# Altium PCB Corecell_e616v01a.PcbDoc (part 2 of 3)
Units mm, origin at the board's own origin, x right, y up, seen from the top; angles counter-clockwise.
Board outline 72.95 x 30.9 mm, 4 copper layers (Top Layer, MidLayer1 - GND, MidLayer2, Bottom Layer), stack 0.637 mm thick; 233 components, 174 nets, 666 pads, 1160 vias.
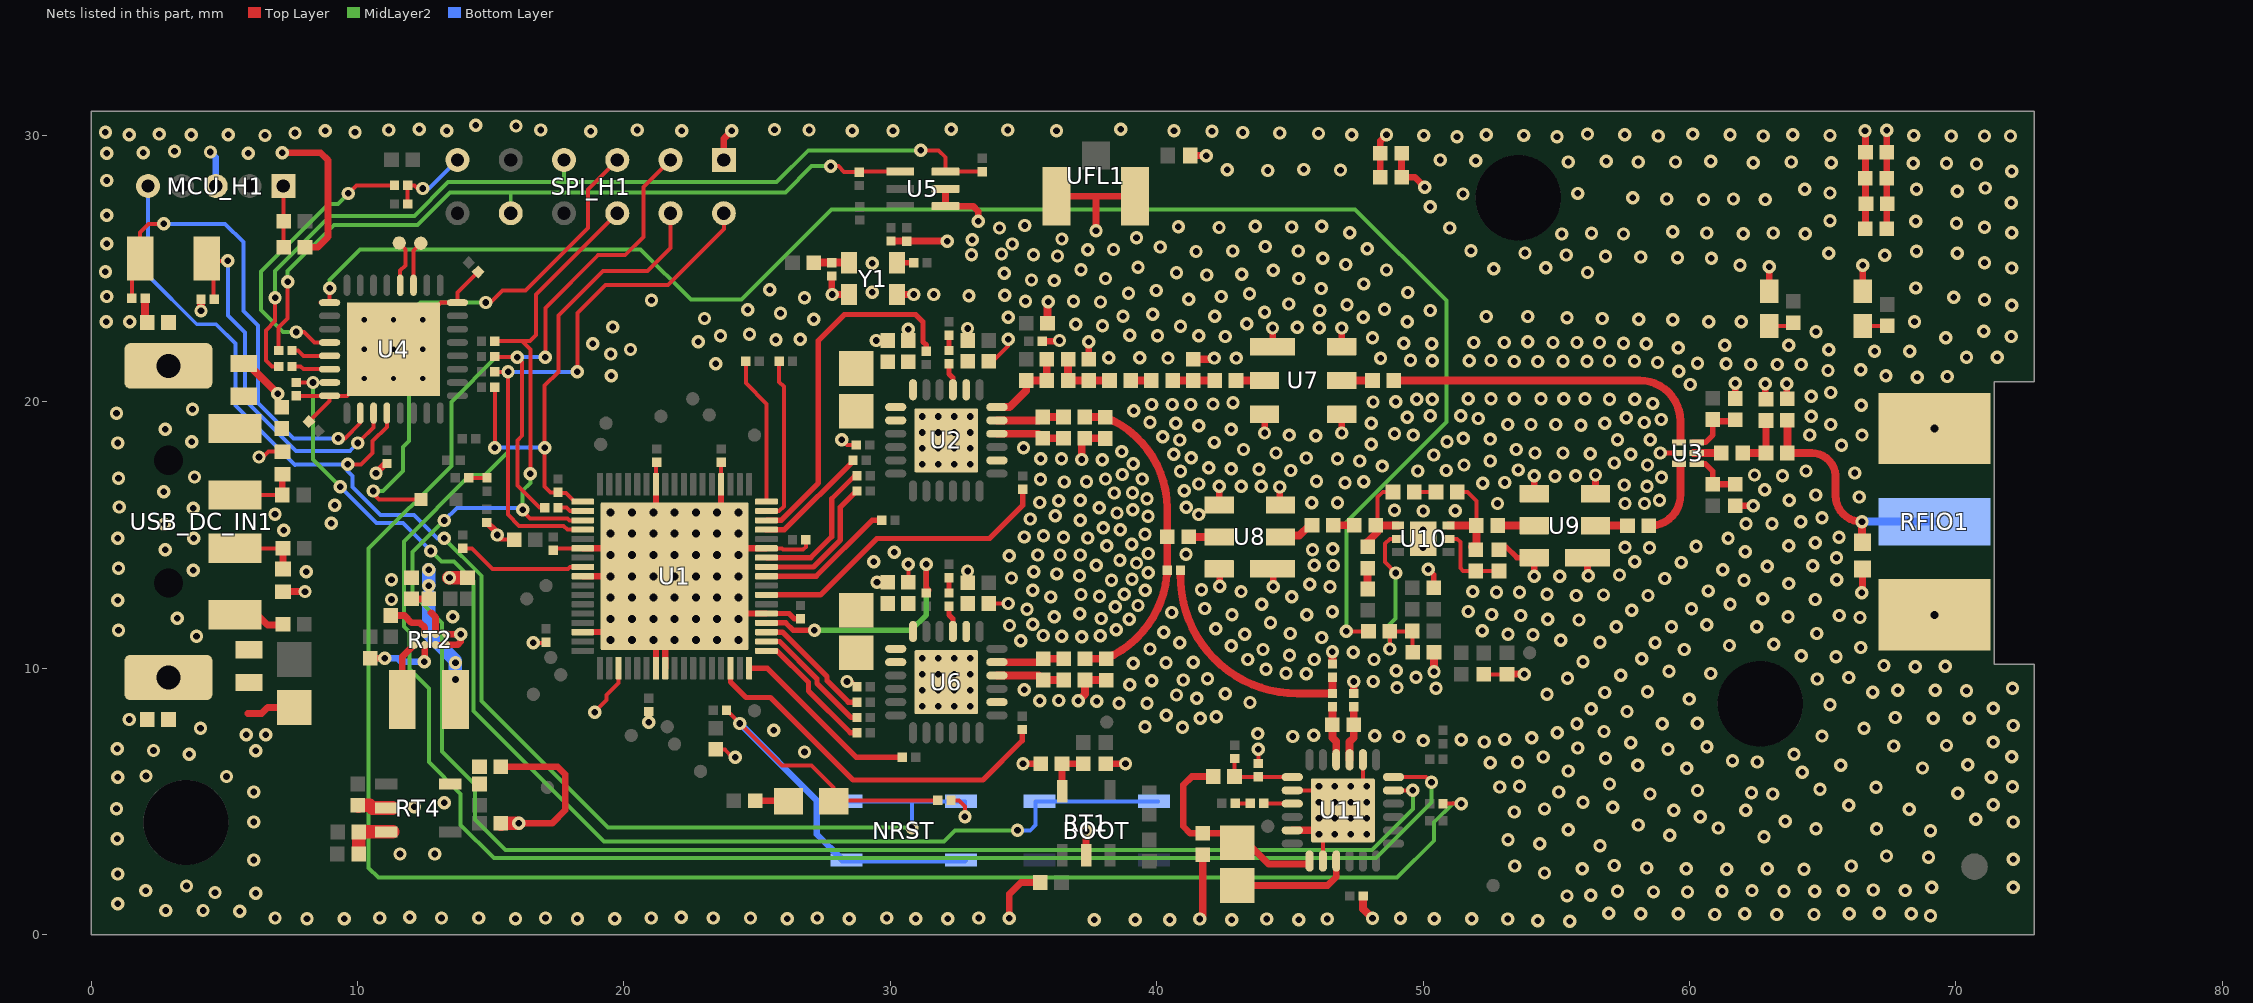
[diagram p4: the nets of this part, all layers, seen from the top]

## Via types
v1: diameter 0.5, hole 0.25, Top Layer to Bottom Layer, tented both sides, 1086 vias
v2: diameter 0.6, hole 0.3, Top Layer to Bottom Layer, tented top, 49 vias
v3: diameter 0.5, hole 0.25, Top Layer to Bottom Layer, 16 vias
v4: diameter 0.5, hole 0.2, Top Layer to Bottom Layer, 9 vias

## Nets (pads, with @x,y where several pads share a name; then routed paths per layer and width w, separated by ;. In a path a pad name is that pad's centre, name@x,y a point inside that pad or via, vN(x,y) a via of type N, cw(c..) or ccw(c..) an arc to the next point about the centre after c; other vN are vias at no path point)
GND: 433MHz.1 433MHz.2 490MHz.1 490MHz.2 920MHz.1 920MHz.2 C1.1 C2.1 C3.1 C4.1 C5.1 C6.1 C7.1 C8.1 C9.1 C10.1 C12.1 C13.1 C14.1 C15.2 C16.2 C17.1 C18.1 C21.1 C22.1 C23.1 C24.1 C29.1 C31.1 C33.2 C34.2 C35.1 C36.1 C37.1 C38.2 C39.2 C40.2 C41.1 C44.1 C45.1 C46.1 C47.1 C48.1 C49.2 C50.1 C51.2 C52.1 C53.1 C54.1 C55.1 C56.1 C58.2 C59.2 C60.2 C61.1 C67.1 C68.2 C69.1 C72.1 C73.1 C74.1 C75.1 D1.2 D2.2 D3.2 D4.2 D6.2 D11.2 FB6.1 FB7.2 FB15.1 LED_PWR.2 LED_RX.2 LED_TX.2 MCU_H1.3 NRST.2 Other.1 Other.2 R8.1 R30.1 R38.2 R59.2 RFIO1.2 RT1.2 RT2.B2 RT2.C1 RT2.D1 RT2.D2 RT4.2 SPI_H1.1 SX1302.1 SX1302.2 SX1303.1 SX1303.2 U1.6 U1.9 U1.15 U1.20 U1.24 U1.25 U1.39 U1.46 U1.55 U1.62 U1.69 U2.7 U2.20 U2.25 U3.2 U4.16 U4.32 U4.33 U5.4 U5.5 U6.7 U6.20 U6.25 U7.1 U7.3 U7.4 U7.6 U8.1 U8.3 U8.4 U8.6 U9.1 U9.3 U9.4 U9.6 U10.7 U11.2 U11.5 U11.8 U11.20 U11.25 UFL1.1 UFL1.2 Y1.1 Y1.2 | length 170
  Top Layer w0.15: v1(6.3,17.925) 6.45,17.925 6.65,18.125 D3.2@7.175,18.125 ; R30.1@7.7,20.225 U4.32@8.95,20.225 ; C12.1@8.173,19.252 8.95,20.029 U4.32@8.95,20.225 ; C16.2@11.25,11.975 C16.2@11.45,11.775 ; C54.1@14.527,24.873 13.75,24.096 U4.16@13.75,23.725 13.125,23.725 13,23.6 12.975,23.6 v4(12.45,23.075) v4(11.35,21.975) v4(10.25,20.875) 9.6,20.225 U4.32@8.95,20.225 ; v1@15.24,14.925 15.34,14.825 C4.1@15.875,14.825 ; v1(16.6,10.95) 17.05,10.95 C7.1@17.075,10.975 ; C5.1@17.35,14.425 17.425,14.5 U1.6@18.45,14.5 ; v1(18.9,8.35) 19.35,8.8 19.35,9 19.8,9.45 U1.20@19.8,10 ; U1.69@19.8,11.35 v2(20.3,11.85) v2(21.1,12.65) 21.2,12.75 21.55,13.1 v2(21.9,13.45) ; U1.69@20.85,14.5 v2(21.1,14.25) ; v1@20.925,7.925 v1(20.925,7.975) C8.1@20.925,8.375 ; U1.69@21.2,14.15 v2(21.9,13.45) ; U1.62@21.2,16.9 21.2,17.7 C1.1@21.225,17.725 ; U1.69@23.3,12.05 v2(22.7,12.65) v2(21.9,13.45) ; C10.1@23.45,6.95 23.784,6.95 24.079,6.655 v1(24.181,6.655) ; C2.1@23.625,17.8 23.65,17.775 C2.1@23.65,17.725 U1.55@23.65,16.9 ; U1.69@23.65,15.2 v2(23.5,15.05) 22.95,14.5 v2(22.7,14.25) v2(21.9,13.45) ; C9.1@23.925,8.35 C9.1@23.85,8.425 v1(24.35,7.925) 25.925,6.35 27.043,6.35 27.873,5.52 27.875,5.52 LED_PWR.2@27.875,5 27.912,5.037 R38.2@31.779,5.037 ; U1.46@25.35,14.5 25.925,14.5 25.975,14.45 26.725,14.45 26.825,14.55 C3.1@26.825,14.825 ; v1(28.175,18.575) 28.375,18.375 C37.1@28.725,18.375 ; C46.1@30.675,13.225 v1(30.675,13.9) ; C41.1@33.7,12.425 v1(34.425,12.425) ; C23.1@33.7,21.525 33.85,21.525 34.425,22.1 v1(34.425,22.35) ; v1@34.976,6.403 v1(34.982,6.409) ; C31.1@43.815,6.422 v1(43.815,6.95) ; U11.2@45.09,5.412 46.09,5.412 46.24,5.412 v3(46.69,4.962) U11.25@46.99,4.662 v3(47.29,4.962) 47.74,5.412 47.74,5.562 U11.20@47.74,6.562 ; U11.8@46.24,2.762 U11.25@46.24,3.762 ; v1(46.596,10.612) v1@46.609,10.625 ; C14.1@52.273,9.769 53.143,9.769 C61.1@53.15,9.777 ; v1@53.795,9.777 v1(53.797,9.775)
  Top Layer w0.152: v1(28.375,9.5) 28.55,9.5 C47.1@28.75,9.3 ; C36.1@30.675,22.3 v1(30.675,22.725)
  Top Layer w0.2: U1.39@25.35,12.05 26.2,12.05 26.4,11.85 C6.1@26.625,11.85 ; v1(50.19,13.716) 50.398,13.509 C68.2@50.398,13.015 ; C67.1@52.682,14.551 52.85,14.551 53.121,14.551 53.521,14.15 U9.6@54.175,14.15 ; v1(58.9,18.077) 59.61,18.077 59.758,18.077 U3.2@59.76,18.075
  Top Layer w0.203: RT2.C1@12.925,10.875 RT2.D1@13.325,10.875
  Top Layer w0.229: U1.15@18.45,11.35 19.5,11.35 U1.69@19.8,11.35 ; U1.9@18.45,13.45 v2(19.5,13.45) v2(20.3,13.45) v2(21.1,13.45) v2(21.9,13.45) ; U1.6@18.45,14.5 19.5,14.5 20.3,14.5 U1.69@20.85,14.5 ; U1.24@21.2,10 21.2,11.05 21.2,11.85 21.2,12.65 U1.69@21.2,12.75 ; U1.69@21.2,14.15 21.2,14.25 21.2,15.05 21.2,15.85 U1.62@21.2,16.9 ; U1.25@21.55,10 21.55,11.05 21.55,11.85 21.55,12.65 U1.69@21.55,13.1 ; U1.69@22.95,14.5 23.5,14.5 24.3,14.5 U1.46@25.35,14.5 ; U1.69@23.3,12.05 23.5,12.05 24.3,12.05 U1.39@25.35,12.05 ; U1.69@23.65,15.2 23.65,15.85 U1.55@23.65,16.9
  Top Layer w0.25: C48.1@27.8,24.725 27.8,24.05 v1(27.825,24.025) Y1.1@28.45,24.025 ; Y1.2@30.25,24.025 v1(30.875,24.025) ; C18.1@35.7,22.275 36.325,22.275 v1(36.35,22.3) ; C21.1@37.45,21.6 v1(37.45,22.25) ; U8.4@42.348,16.127 v1(42.348,16.827) ; v1(42.373,13.077) 42.373,13.727 U8.6@42.373,13.752 ; v1(44.05,18.83) U7.3@44.05,19.53 ; U7.1@44.35,22.07 v1(44.35,22.77) ; v1(44.373,13.052) 44.373,13.727 U8.1@44.373,13.752 ; U8.3@44.623,16.102 44.623,16.127 v1(44.623,16.802) ; v1(46.95,18.83) U7.4@46.95,19.53 ; U7.6@46.95,22.07 v1(46.95,22.77) ; v1(54.175,13.45) U9.6@54.175,14.15 ; U9.4@54.175,16.5 U9.4@54.175,16.55 v1@54.175,17.2 ; v1@56.175,13.45 56.175,13.475 U9.1@56.175,14.15 ; U9.3@56.475,16.55 v1(56.475,17.25) ; C39.2@61.725,16.1 v1(62.4,16.1) ; C24.1@61.725,20.075 C24.1@61.725,20.125 v1(61.725,20.7) ; C33.2@62.85,20.05 62.85,20.1 v1(62.85,20.675) ; LED_RX.2@63,24.15 v1(63,25.075) ; C34.2@63.65,20.05 63.65,20.11 v1(63.65,20.675) ; LED_TX.2@66.5,24.2 v1(66.5,25.125)
  Top Layer w0.254: 5.875,8.3 6.4,8.3 6.625,8.525 C15.2@7.625,8.525 ; v1(7.175,29.35) 8.61,29.35 8.89,29.07 8.89,26.195 8.893,26.192 8.501,25.8 C56.1@8.025,25.8 ; D2.2@7.2,12.875 v1(8.025,12.875) ; v1(10.693,17.323) 11.053,17.682 C13.1@11.104,17.682 ; C16.2@11.25,11.975 11.76,11.975 12.032,11.703 12.342,11.703 12.525,11.52 RT2.B2@12.525,11.275 ; RT2.D1@13.325,10.875 13.753,10.875 13.869,10.992 13.869,11.269 v1(13.875,11.275) RT2.D2@13.325,11.275 ; R8.1@14.85,15.469 v1@15.175,15.144 ; C58.2@15.375,6.3 17.501,6.3 17.795,6.006 17.795,4.67 17.3,4.175 v1(16.05,4.175) ; SPI_H1.1@23.75,29.08 23.75,29.877 v1(24.05,30.177) ; C40.2@30.022,26.039 30.615,26.039 C38.2@30.622,26.032 v1(32.131,26.032) ; U5.5@32.072,27.993 U5.4@32.072,27.343 33.107,27.343 33.297,27.153 33.297,26.782 v1@33.297,26.739 ; v1(34.468,0.61) 34.468,1.52 34.904,1.956 C51.2@35.628,1.956 ; v1(34.982,6.409) C49.2@35.643,6.409 ; UFL1.2@36.238,27.717 37.719,27.717 ; RT1.2@37.349,3.229 v1(37.349,3.889) ; v1@37.719,26.375 v1(37.719,26.416) 37.719,27.717 ; C50.1@38.09,6.409 v1(38.828,6.409) ; UFL1.1@39.188,27.717 37.719,27.717 ; D11.2@41.204,29.242 D11.2@41.264,29.242 v1(41.859,29.242) ; SX1303.2@48.398,28.432 48.393,28.437 SX1302.2@48.393,29.325 48.393,29.793 v1(48.625,30.025) ; SX1302.1@49.193,29.325 49.193,28.437 SX1303.1@49.198,28.432 49.687,28.432 v1(50.068,28.051) ; C61.1@53.15,9.777 v1@53.795,9.777 ; v1(66.472,12.833) 66.497,12.859 D1.2@66.497,13.724 ; v1(66.593,30.177) 66.608,30.162 433MHz.2@66.608,29.367 66.608,28.388 66.608,27.432 66.608,26.505 Other.2@66.6,26.497 ; Other.1@67.4,26.497 67.408,26.505 67.408,27.432 67.408,28.388 433MHz.1@67.408,29.367 v1(67.408,30.19)
  Top Layer w0.293: C69.1@2.025,23.891 2.025,23.05 FB6.1@2.1,22.975 ; v1@4.115,23.405 v1(4.121,23.412) C60.2@4.121,23.849 ; D4.2@5.725,21.438 5.863,21.438 v1(7,20.3) ; C17.1@35.9,22.95 35.9,23.725 v1(35.925,23.75) ; v1(37.059,8.775) 37.31,9.027 C45.1@37.31,9.557 38.093,9.557 C44.1@38.1,9.55 ; v1(37.186,17.831) 37.186,18.513 C35.1@37.303,18.631 38.068,18.631 C29.1@38.075,18.625 ; C22.1@41.375,21.6 42.123,21.6 v1(42.164,21.641) ; v1(41.612,0.584) 41.725,0.698 C74.1@41.725,3 ; U11.5@45.09,3.912 46.09,3.912 46.24,3.912 v3(46.69,4.362) U11.25@46.99,4.662 ; C72.1@46.596,10.156 v1(46.596,10.612) ; C73.1@47.396,9.05 v1(47.396,9.5) ; C75.1@47.748,1.448 47.748,0.962 v1(48.1,0.61) ; v1(50.411,9.866) R59.2@50.411,10.6
  Top Layer w0.508: C59.2@10.025,4.825 C59.2@10,4.85 10.45,4.85 10.55,4.75 RT4.2@11.073,4.75 RT4.2@11.325,4.75 ; v1@13.425,13.4 v1(13.45,13.4) C53.1@14.125,13.4 ; C55.1@15.375,4.15 C55.1@15.4,4.15 ; C55.1@15.375,4.175 v1(16.05,4.175)
  Bottom Layer w0.25: v1(4.475,29.375) 4.675,29.175 MCU_H1.3@4.675,28.1 ; v1(24.35,7.925) 27.238,5.037 27.238,3.762 28.2,2.8 NRST.2@28.35,2.8 NRST.2@32.65,2.8 NRST.2@32.8,2.8
  other v1: 55.5,0.496 54.3,0.521 37.66,0.559 39.192,0.559 40.487,0.559 42.812,0.559 45.337,0.559 8.103,0.597 9.503,0.597 15.928,0.597 18.253,0.597 19.653,0.597 26.128,0.597 28.453,0.597 30.95,0.597 32.15,0.597 44.137,0.584 46.406,0.584 50.425,0.598 51.825,0.598 53.175,0.584 6.903,0.622 10.828,0.622 13.153,0.622 14.553,0.622 17.053,0.622 21.028,0.622 23.353,0.622 24.753,0.622 27.253,0.622 29.863,0.623 33.32,0.623 49.149,0.61 11.953,0.647 22.153,0.647 69.05,0.7 60.95,0.75 63.275,0.75 64.675,0.75 58.175,0.775 59.575,0.775 62.075,0.775 66,0.775 68.325,0.775 56.975,0.8 67.125,0.8 5.575,0.875 2.8,0.9 4.2,0.9 1,1.15 55.4,1.45 56.3,1.475 6.175,1.55 4.65,1.575 57.3,1.625 58.65,1.6 59.925,1.6 61.225,1.625 63.55,1.625 64.7,1.625 2.05,1.65 62.35,1.65 65.775,1.65 68.1,1.65 66.9,1.675 69.1,1.775 72.15,1.775 3.575,1.825 1,2.275 54.556,2.311 61.4,2.45 64.3,2.45 55.979,2.475 59.875,2.475 62.925,2.475 58.4,2.5 53.442,2.575 66.075,2.575 57.175,2.591 6.1,2.8 72.15,2.825 68.975,2.9 67.4,2.95 11.592,3.023 12.898,3.023 56.642,3.327 54.379,3.412 53.188,3.556 0.975,3.6 62.8,3.675 59.258,3.725 69.05,3.9 55.445,3.937 64.75,3.975 67.025,3.975 61.075,4 58.077,4.115 6.1,4.225 72.15,4.225 63.6,4.25 70.75,4.325 60.401,4.42 53.425,4.597 59.411,4.662 62.108,4.662 54.559,4.716 68.25,4.7 0.95,4.725 12.125,4.8 57.122,4.775 65.975,4.85 71.4,4.875 13.25,4.95 56.004,4.97 58.522,5.275 63.125,5.275 70.075,5.3 62.332,5.326 6.1,5.35 55.093,5.351 60.3,5.41 64.9,5.45 67,5.525 52.883,5.537 72.125,5.55 53.619,5.562 57,5.65 1,5.9 71.325,5.9 5.08,5.935 2.057,5.95 64.237,6.088 55.445,6.138 59.898,6.24 68.75,6.25 58.057,6.35 65.675,6.35 70.45,6.375 52.527,6.443 53.543,6.469 62.55,6.477 61.618,6.528 56.849,6.621 54.506,6.662 72.1,6.675 3.683,6.773 63.922,6.773 26.775,6.85 6.175,6.9 2.337,6.909 0.975,6.975 59.197,6.96 55.804,7.002 60.655,7.053 67.675,7.075 69.65,7.1 57.8,7.205 52.299,7.231 71.4,7.225 50.011,7.281 51.435,7.307 53.066,7.325 54.077,7.383 45.11,7.434 49.098,7.434 48.184,7.459 64.973,7.45 45.898,7.48 5.825,7.5 6.55,7.5 43.79,7.544 55.042,7.575 56.794,7.621 25.625,7.675 4.1,7.75 66.55,7.75 40.97,7.788 39.558,7.8 72.15,7.85 55.775,7.917 58.979,7.917 60.295,7.929 1.425,8.075 41.631,8.125 69.15,8.125 70.5,8.125 67.725,8.15 42.24,8.175 40.361,8.23 57.658,8.375 56.312,8.475 71.4,8.5 31.2,8.575 31.8,8.575 32.4,8.575 33,8.575 65.275,8.625 38.585,8.687 39.638,8.687 43.503,8.712 35.611,8.775 37.75,8.763 36.325,8.788 59.99,8.839 41.508,8.873 40.742,8.992 54.65,9.025 42.578,9.042 56.825,9.084 66.875,9.1 58.425,9.119 70.4,9.15 31.2,9.175 31.8,9.175 32.4,9.175 33,9.175 67.825,9.175 69.225,9.175 35.027,9.195 50.484,9.25 72.125,9.25 49.022,9.271 38.989,9.373 48.133,9.5 39.819,9.525 40.996,9.557 64.795,9.594 41.908,9.601 55.42,9.627 65.975,9.65 49.733,9.656 57.427,9.728 31.2,9.775 31.8,9.775 32.4,9.775 33,9.775 45.618,9.795 60.8,9.8 44.856,9.804 59.233,9.881 48.997,9.907 44.103,9.957 68.475,10.05 69.6,10.075 67.3,10.1 39.119,10.185 40.348,10.2 41.377,10.225 56.004,10.243 43.421,10.325 45.911,10.325 48.158,10.325 58.207,10.35 31.2,10.375 31.8,10.375 32.4,10.375 33,10.375 65.5,10.425 64.2,10.468 44.983,10.49 47.375,10.6 43.993,10.7 59.8,10.7 39.751,10.719 66.425,10.775 42.799,10.841 61.5,10.85 63.17,10.9 40.869,10.95 58.71,10.95 56.642,10.973 34.9,11.032 55.169,11.046 46.196,11.151 3.95,11.2 37.186,11.185 35.738,11.225 36.433,11.201 37.875,11.212 54.127,11.25 43.307,11.269 45.009,11.3 53.188,11.278 64.775,11.3 40.263,11.35 1.025,11.425 52.222,11.405 38.481,11.445 42.215,11.481 57.252,11.55 59.325,11.55 62.525,11.55 34.475,11.6 60.65,11.625 35.35,11.65 44.272,11.703 55.852,11.811 38.964,11.836 54.683,11.836 3.225,11.875 37.922,11.862 66.4,11.9 13.575,11.925 36.15,11.925 63.7,11.925 53.667,11.975 65.625,11.975 42.824,12.005 45.628,12.005 37.109,12.038 52.578,12.014 40.564,12.09 46.596,12.12 51.7,12.125 57.833,12.175 35.128,12.215 60.075,12.225 41.808,12.243 38.447,12.307 39.3,12.355 43.942,12.4 61.525,12.4 1,12.55 11.275,12.575 64.725,12.575 62.75,12.6 36.017,12.675 45.071,12.675 37.85,12.7 55.75,12.725 56.775,12.75 58.445,12.725 37.16,12.762 54.65,12.775 38.786,12.776 52.756,12.85 43.168,12.875 51.867,12.875 53.619,12.852 60.7,12.9 35.35,12.925 39.569,12.93 41.679,12.949 46.507,13.052 45.745,13.15 63.725,13.175 38.303,13.3 62.05,13.3 11.275,13.325 65.525,13.325 39.075,13.337 59.076,13.365 34.55,13.386 55.125,13.45 37.1,13.475 56.2,13.475 57.375,13.5 36.246,13.538 39.683,13.584 8.075,13.625 35.388,13.614 3.825,13.675 61.25,13.7 1.025,13.75 62.925,13.825 45.911,13.858 46.626,13.853 64.625,13.85 37.725,13.868 39.243,13.945 59.69,13.97 29.375,14 57.95,14 38.619,14.046 65.522,14.14 34.468,14.224 35.538,14.25 36.373,14.249 37.135,14.249 41.097,14.275 39.683,14.306 30.15,14.35 62.1,14.375 2.775,14.45 45.847,14.45 46.609,14.478 58.5,14.525 49.994,14.53 57.579,14.538 60.249,14.577 38.125,14.6 63.725,14.6 39.065,14.65 64.725,14.707 1,14.875 3.85,14.875 61.45,14.875 37.414,14.884 35.027,14.927 36.503,14.91 65.613,14.914 35.75,14.975 15.24,14.997 39.558,15.026 7.225,15.175 49.994,15.187 38.633,15.2 37.998,15.275 2.75,15.4 9.017,15.441 62.125,15.425 63.1,15.425 64.175,15.5 37.135,15.554 35.25,15.6 64.973,15.65 36.19,15.719 39.673,15.703 41.575,15.766 6.9,15.775 38.506,15.824 50.011,15.9 51.206,15.912 39.1,15.948 48.925,15.926 3.825,16 1.05,16.05 37.838,16.027 41.103,16.044 9.144,16.118 52.792,16.18 57.582,16.181 58.315,16.18 35.611,16.218 45.822,16.205 46.787,16.205 36.325,16.283 37.135,16.3 58.877,16.3 63.75,16.3 39.638,16.361 66.375,16.425 64.745,16.5 38.405,16.575 39.091,16.586 2.725,16.625 41.037,16.662 62.825,16.7 43.173,16.827 43.923,16.827 58.405,16.825 57.55,16.875 41.575,16.912 47.066,16.963 52.236,16.942 36.525,16.988 53.061,16.967 37.363,16.993 47.775,17 46,17.018 35.636,17.094 38.075,17.1 39.453,17.1 1.025,17.125 58.952,17.169 3.875,17.175 54.95,17.2 54.175,17.225 55.725,17.225 63.495,17.225 38.71,17.269 62.443,17.25 66.2,17.325 40.894,17.387 45.034,17.422 49.8,17.4 50.875,17.422 64.375,17.4 53.569,17.442 43.84,17.466 42.8,17.49 41.95,17.525 48.463,17.586 51.537,17.625 58.425,17.625 31.2,17.65 31.8,17.65 32.4,17.65 33,17.65 39.119,17.675 57.175,17.7 47.625,17.775 52.527,17.78 37.95,17.825 35.65,17.856 36.424,17.856 46.787,17.856 41.3,17.9 45.618,17.887 50.4,18 40.64,18.031 57.8,18.025 56.275,18.05 44.475,18.075 54.2,18.075 55.25,18.075 38.684,18.131 43.256,18.212 53.492,18.212 31.2,18.25 31.8,18.25 32.4,18.25 33,18.25 35.001,18.275 65.71,18.364 48.05,18.4 1,18.45 42.164,18.475 3.775,18.5 50.9,18.5 40.869,18.567 57.3,18.575 58.525,18.575 52.525,18.6 51.511,18.63 40.227,18.683 45.975,18.725 44.975,18.75 49.625,18.75 64.516,18.752 66.475,18.75 48.925,18.8 31.2,18.85 31.8,18.85 32.4,18.85 33,18.85 2.775,18.975 42.8,18.975 41.575,19.1 55.925,19.125 53.175,19.15 54.05,19.15 54.975,19.15 65.3,19.15 40.72,19.2 48.05,19.2 56.825,19.2 58.3,19.225 39.751,19.231 58.938,19.336 52.075,19.375 57.625,19.4 49.4,19.425 31.2,19.45 31.8,19.45 32.4,19.45 33,19.45 50.275,19.475 64.567,19.456 51.41,19.482 0.95,19.575 39.141,19.663 3.8,19.725 66.45,19.875 39.819,19.9 40.584,19.9 41.275,19.9 42.113,19.914 58.623,19.939 42.867,19.964 48.123,19.994 48.974,20 49.759,20.1 50.35,20.1 52.55,20.11 53.425,20.11 55.278,20.11 56.08,20.11 57,20.1 57.948,20.091 51.7,20.117 54.425,20.117 64.575,20.212 65.3,20.35 60.035,20.65 68.55,20.925 69.675,20.95 19.525,20.975 67.375,20.975 59.6,21.15 65.2,21.175 66.425,21.2 62.3,21.4 63.3,21.4 64.2,21.4 23.444,21.425 61.375,21.425 60.3,21.45 58.8,21.475 53.421,21.514 54.302,21.514 55.25,21.525 56.157,21.525 57,21.531 57.937,21.525 50.35,21.541 51.729,21.539 52.55,21.55 49.525,21.565 48.405,21.637 38.202,21.652 39.364,21.65 40.426,21.641 42.991,21.641 70.4,21.675 71.55,21.675 19.5,21.793 66.95,21.9 68.275,21.9 20.244,21.965 65.225,21.95 59.575,22.025 61.325,22.125 63.725,22.125 18.825,22.175 50.325,22.175 58.375,22.175 49.275,22.2 57.525,22.2 51.9,22.225 53.05,22.225 54.875,22.225 55.775,22.225 56.625,22.225 22.784,22.25 53.925,22.25 25.705,22.327 26.612,22.352 48.1,22.4 69.625,22.4 42.575,22.45 72.075,22.45 23.625,22.475 40.03,22.475 41.575,22.475 38.989,22.5 24.714,22.53 64.75,22.625 71.05,22.65 46.1,22.775 45.275,22.8 19.583,22.809 40.894,22.835 37.965,22.86 36.957,22.912 43.375,22.925 0.559,23 1.45,23 49.4,23 60.725,23 61.95,23 68.45,23 59.375,23.076 27.125,23.1 58.1,23.101 23.025,23.126 56.725,23.126 55.4,23.151 34.425,23.175 47.75,23.175 52.375,23.2 53.925,23.201 38.735,23.216 42.175,23.216 39.85,23.292 25.875,23.325 44.05,23.363 46.126,23.425 50.275,23.425 24.65,23.45 48.55,23.475 47.142,23.641 72.1,23.625 44.958,23.673 37.89,23.749 35.075,23.775 36.875,23.775 21.031,23.812 71.075,23.825 41.199,23.851 26.775,23.9 69.925,23.925 0.584,23.95 32.95,23.975 42.418,23.952 34.3,24 31.625,24.025 43.485,24.05 38.938,24.075 49.425,24.1 29.325,24.118 39.98,24.181 25.476,24.206 46.177,24.25 68.5,24.275 47.775,24.425 36.15,24.55 35.3,24.575 38.075,24.629 45.337,24.629 41.885,24.759 43.197,24.79 34.275,24.825 40.742,24.841 56.175,24.851 0.533,24.881 37.16,24.957 44.373,24.943 48.625,24.95 52.65,25 54.607,25.034 72.1,25.025 39.3,25.05 61.897,25.121 47.092,25.155 29.316,25.201 71.075,25.225 46.228,25.384 60.824,25.385 59.549,25.41 58.174,25.435 36.275,25.475 56.849,25.46 33.05,25.525 35.375,25.525 55.374,25.51 67.327,25.506 34.175,25.55 65.225,25.575 70.05,25.575 53.824,25.585 41.478,25.643 68.525,25.65 42.85,25.658 45.314,25.658 51.8,25.675 37.414,25.705 38.379,25.719 47.9,25.75 40.132,25.811 44.069,25.832 34.572,25.925 0.584,25.933 33.071,26.086 36.442,26.111 39.243,26.162 55.2,26.3 57.525,26.3 62.025,26.311 64.35,26.311 56.325,26.325 60.65,26.336 63.15,26.336 47.244,26.35 72.1,26.35 59.375,26.386 34.097,26.525 42.342,26.542 51,26.525 45.071,26.56 71.075,26.55 40.815,26.573 43.696,26.585 46.196,26.585 35.052,26.617 70.025,26.7 33.299,26.782 68.5,26.775 65.278,26.8 0.584,26.999 50.275,27.325 72.075,27.475 60.525,27.591 62.85,27.591 59.15,27.616 61.65,27.616 57.875,27.666 51.5,27.8 55.801,27.822 65.278,27.838 70.05,27.9 64.325,27.975 68.525,27.975 71.1,28.025 0.584,28.31 72.1,28.65 44.171,28.68 46.9,28.698 42.644,28.711 45.525,28.723 70.775,28.925 68.4,28.95 69.65,28.95 62.4,28.975 65.325,28.975 55.448,29 58.075,29 59.475,29 63.825,29 56.875,29.025 60.8,29.025 51.975,29.05 50.65,29.075 0.584,29.331 5.9,29.325 1.95,29.35 3.125,29.4 51.275,29.95 55.025,29.95 58.825,29.975 62.775,29.975 69.825,29.975 71.075,29.975 72.05,29.975 6.525,30 50.025,30 53.775,30 65.275,30 68.425,30 1.425,30.025 3.75,30.025 5.15,30.025 47.325,30.025 52.375,30.025 57.575,30.025 61.525,30.025 63.875,30.025 2.55,30.05 56.175,30.05 60.125,30.05 7.65,30.093 44.623,30.092 46.075,30.075 43.231,30.108 0.533,30.124 9.906,30.124 8.788,30.169 13.35,30.169 18.75,30.152 42.075,30.154 22.175,30.177 28.572,30.177 30.097,30.175 36.238,30.175 40.65,30.175 11.176,30.201 16.875,30.201 20.5,30.202 25.65,30.219 26.95,30.201 34.404,30.201 12.319,30.226 32.283,30.226 38.644,30.226 15.95,30.353 14.43,30.378
  other v2: 19.5,11.05 20.3,11.05 21.1,11.05 21.9,11.05 22.7,11.05 23.5,11.05 24.3,11.05 19.5,11.85 21.1,11.85 21.9,11.85 22.7,11.85 23.5,11.85 24.3,11.85 19.5,12.65 20.3,12.65 21.9,12.65 23.5,12.65 24.3,12.65 22.7,13.45 23.5,13.45 24.3,13.45 19.5,14.25 20.3,14.25 21.9,14.25 23.5,14.25 24.3,14.25 19.5,15.05 20.3,15.05 21.1,15.05 21.9,15.05 22.7,15.05 24.3,15.05 19.5,15.85 20.3,15.85 21.1,15.85 21.9,15.85 22.7,15.85 23.5,15.85 24.3,15.85
  other v3: 46.09,3.762 46.69,3.762 47.29,3.762 47.89,3.762 46.09,4.362 47.29,4.362 47.89,4.362 46.09,4.962 47.89,4.962 46.09,5.562 46.69,5.562 47.29,5.562 47.89,5.562
  other v4: 11.35,20.875 12.45,20.875 10.25,21.975 12.45,21.975 10.25,23.075 11.35,23.075
GPS_NRST: R34.2 U4.28 | length 10.9
  Top Layer w0.15: v1(7.696,22.618) 7.986,22.618 8.379,22.225 U4.28@8.95,22.225 ; v1(9.65,27.822) 9.955,28.127 R34.2@11.383,28.127
  MidLayer2 w0.15: v1(7.696,22.618) 7.207,22.618 6.375,23.45 6.375,24.892 8.915,27.432 9.26,27.432 v1(9.65,27.822)
HOST_CSN: R1.1 R48.2 SPI_H1.4 U1.1 | length 19
  Top Layer w0.15: v1(15.15,18.275) R48.2@15.15,20.55 ; R1.1@17.525,16.575 17.825,16.575 18.15,16.25 U1.1@18.45,16.25 ; R1.1@17.525,16.6 17.25,16.6 17.025,16.825 v1(17.025,18.275) 17.025,20.606 17.545,21.126 17.545,23.235 19.222,24.912 20.889,24.912 21.75,25.773 SPI_H1.4@21.75,27.08
  MidLayer2 w0.15: v1@15.121,18.275 v1(15.15,18.275)
  Bottom Layer w0.15: v1(15.15,18.275) v1(17.025,18.275)
HOST_I2C_SCL: R29.1 R54.2 SPI_H1.10 U5.1 | length 28.6
  Top Layer w0.15: R54.2@7.04,21.925 7.04,22.79 7.376,23.126 v1(7.376,24.511) ; v1(27.762,28.844) 28.047,28.844 28.268,28.622 R29.1@28.831,28.622 ; R29.1@28.845,28.66 28.857,28.647 28.861,28.643 U5.1@30.372,28.643
  MidLayer2 w0.15: v1(7.376,24.511) 7.376,24.905 9.116,26.645 12.254,26.645 13.473,27.864 15.748,27.864 ; SPI_H1.10@15.75,27.08 15.75,27.862 15.748,27.864 ; 16.75,27.85 16.764,27.864 ; v1(27.762,28.844) 27.044,28.844 26.064,27.864 16.764,27.864 ; 15.748,27.864 16.764,27.864
HOST_I2C_SDA: R51.1 R53.2 SPI_H1.7 U5.6 | length 34.1
  Top Layer w0.15: v1(6.903,23.901) 6.903,23.035 6.553,22.685 6.553,21.551 6.779,21.325 R53.2@7.04,21.325 R53.2@7.065,21.325 ; v1(31.14,29.439) 31.814,29.439 32.072,29.18 U5.6@32.072,28.643 33.447,28.643 33.501,28.643 R51.1@33.503,28.644
  MidLayer2 w0.15: v1(6.903,23.901) 6.903,24.917 8.961,26.975 12.132,26.975 13.402,28.245 17.755,28.245 ; SPI_H1.7@17.75,29.08 17.75,28.249 17.755,28.245 ; v1(31.14,29.439) 26.919,29.439 25.725,28.245 17.755,28.245
HOST_MISO: R2.2 R49.1 R63.2 SPI_H1.3 | length 83.6
  Top Layer w0.15: R49.1@15.15,21.7 15.175,21.675 v1(16,21.675) 16.175,21.5 16.175,18.725 16,18.55 16,16.85 16.825,16.025 R2.2@17.025,16.025 ; v1(17.05,21.675) 17.05,23.527 19.025,25.502 20.041,25.502 20.726,26.187 20.726,28.056 SPI_H1.3@21.75,29.08 ; R63.2@50.75,4.912 v1(51.435,4.912) v1@51.473,4.912
  MidLayer2 w0.15: v1(16,21.675) 15.198,21.675 13.519,19.996 13.519,17.591 10.414,14.485 10.414,2.497 10.778,2.134 49.022,2.134 50.419,3.531 50.419,4.216 51.115,4.912 v1(51.435,4.912)
  Bottom Layer w0.15: v1(16,21.675) v1(17.05,21.675)
HOST_MOSI: R37.1 SPI_H1.6 U1.3 U11.17 | length 70.2
  Top Layer w0.15: R37.1@15.15,22.275 16.175,22.275 ; v1(16.2,15.95) 16.2,15.9 16.475,15.625 17.875,15.625 17.95,15.55 U1.3@18.4,15.55 ; v1(16.485,17.297) 16.485,21.965 16.175,22.275 ; 18.11,25.44 16.7,24.03 16.7,22.5 16.475,22.275 16.175,22.275 ; 18.11,25.44 SPI_H1.6@19.75,27.08 ; U11.17@48.89,5.412 v1(49.613,5.412)
  MidLayer2 w0.15: v1(13.25,15.545) 12.061,14.356 12.061,12.81 13.175,11.696 13.175,6.866 14.4,5.641 14.4,4.324 15.549,3.175 48.082,3.175 49.613,4.706 v1(49.613,5.412) ; v1@16.13,16.02 v1(16.2,15.95) 16.2,16.675 16.485,16.96 v1(16.485,17.297)
  Bottom Layer w0.15: v1(13.25,15.545) 13.725,16.02 16.13,16.02 v1(16.2,15.95)
HOST_SCK: R50.2 SPI_H1.2 U1.4 U11.18 | length 81.1
  Top Layer w0.15: R50.2@15.15,21.125 v1(15.65,21.125) 15.65,15.761 16.066,15.345 17.73,15.345 17.875,15.2 U1.4@18.45,15.2 ; v1(18.25,21.125) 18.25,23.33 19.304,24.384 21.647,24.384 23.75,26.487 SPI_H1.2@23.75,27.08 ; U11.18@48.89,5.912 48.9,5.922 48.904,5.918 50.114,5.918 v1(50.317,5.715)
  MidLayer2 w0.15: v1(15.65,21.125) 15.65,18.111 14.783,17.244 14.221,17.244 11.738,14.76 11.738,11.567 11.95,11.354 11.95,9.967 12.677,9.24 12.677,6.475 13.869,5.282 13.869,4.114 15.113,2.87 48.235,2.87 50.317,4.953 v1(50.317,5.715)
  Bottom Layer w0.15: v1(15.65,21.125) v1(18.25,21.125)
HOST_SX1302_RESET: D5.1 SPI_H1.5 | length 20.4
  Top Layer w0.15: v1@10.592,16.543 10.803,16.332 D5.1@12.38,16.332 ; v1(14.808,23.725) 14.987,23.725 15.443,24.181 16.302,24.181 18.644,26.522 18.644,27.974 SPI_H1.5@19.75,29.08
  MidLayer2 w0.15: v1(10.592,16.65) 10.96,16.65 11.711,17.4 11.711,18.298 11.938,18.525 11.938,23.294 12.369,23.725 v1(14.808,23.725)
LNA_ON: R28.2 U4.25 | length 62
  Top Layer w0.15: U4.25@8.609,23.725 U4.25@8.95,23.725 v1(8.95,24.259) ; v1(47.118,11.382) R28.2@47.953,11.382
  MidLayer2 w0.15: v1(8.95,24.259) 8.95,24.58 10.095,25.725 20.622,25.725 22.508,23.838 24.409,23.838 27.798,27.227 47.448,27.227 50.875,23.8 50.875,19.25 47.118,15.493 v1(47.118,11.382)
MCU_BOOT: BOOT.2 R30.2 U4.31 | length 45.2
  Top Layer w0.15: R30.2@7.7,20.725 v1(8.325,20.725)
  MidLayer2 w0.15: v1(8.325,20.725) 8.325,17.837 v1(9.347,16.815) ; v1@12.641,14.367 v1@12.679,14.329 ; v1(12.751,14.4) 13.146,14.005 13.62,14.005 14.352,13.273 14.352,8.398 19.25,3.5 32.018,3.5 32.429,3.912 v1(34.776,3.912)
  Bottom Layer w0.15: v1(9.347,16.815) 10.717,15.445 11.706,15.445 v1(12.751,14.4) ; v1(34.776,3.912) 35.252,3.912 35.45,4.109 35.45,5 BOOT.2@35.6,5 BOOT.2@39.9,5 BOOT.2@40.05,5
MCU_I2C_SCL: R54.1 U4.29 | length 1.5
  Top Layer w0.15: R54.1@7.54,21.925 7.763,21.925 7.963,21.725 U4.29@8.95,21.725
MCU_I2C_SDA: R53.1 U4.30 | length 1.5
  Top Layer w0.15: R53.1@7.54,21.325 7.863,21.325 7.963,21.225 U4.30@8.95,21.225
MCU_NRESET: MCU_H1.5 NRST.1 R38.1 U4.4 | length 55.2
  Top Layer w0.15: v1(9.627,17.653) 10.136,17.653 10.566,18.083 10.566,18.522 11.1,19.056 U4.4@11.1,19.575 ; R38.1@32.279,5.037 32.578,5.037 32.8,4.815 v1(32.8,4.42)
  MidLayer2 w0.15: v1(13.25,14.875) 14.656,13.469 14.656,8.763 19.406,4.013 v1(30.81,4.013)
  Bottom Layer w0.15: MCU_H1.5@2.135,28.1 2.125,28.09 2.125,24.748 3.962,22.911 4.686,22.911 5.41,22.186 5.41,19.865 7.65,17.625 7.678,17.653 v1(9.627,17.653) 9.627,17.399 9.804,17.221 9.804,16.806 10.86,15.75 12.125,15.75 13,14.875 v1(13.25,14.875) ; NRST.1@28.2,5 NRST.1@28.35,5 30.825,5 ; v1(30.81,4.013) 30.81,4.965 30.8,4.975 30.825,5 ; v1(32.8,4.42) 32.8,5 NRST.1@32.65,5 30.825,5
MCU_UART_RX: MCU_UART_RX.1 U4.20 | length 1.8
  Top Layer w0.15: MCU_UART_RX.1@11.562,25.963 11.8,25.725 11.8,25.121 11.6,24.921 U4.20@11.6,24.375
MCU_UART_TX: MCU_UART_TX.1 U4.19 | length 1.7
  Top Layer w0.15: U4.19@12.1,24.375 12.1,25.675 MCU_UART_TX.1@12.375,25.95
NetC11_1: C11.1 C22.2 L3.2 | length 1.6
  Top Layer w0.293: L3.2@40.6,20.8 C22.2@41.375,20.8 C11.1@42.175,20.8
NetC11_2: C11.2 U7.2 | length 1.1
  Top Layer w0.293: C11.2@42.975,20.8 U7.2@44.05,20.8
NetC19_1: C19.1 C20.2 C21.2 L2.2 | length 2.3
  Top Layer w0.293: C19.1@36.675,21.6 L2.2@36.675,20.8 C21.2@37.45,20.8 C20.2@38.225,20.8
NetC19_2: C19.2 L1.1 L2.1 U2.24 | length 3.3
  Top Layer w0.293: U2.24@34,19.8 34.475,19.8 35.1,20.425 L1.1@35.1,20.8 L2.1@35.875,20.8 ; L2.1@35.875,20.825 C19.2@35.875,21.6
NetC20_1: C20.1 L3.1 | length 0.8
  Top Layer w0.293: C20.1@39.025,20.8 L3.1@39.8,20.8
NetC23_2: C23.2 L4.1 R17.2 U2.2
  other v1: 29.475,22.3 32.9,22.75
NetC24_2: C24.2 R18.1 U3.6 | length 2.2
  Top Layer w0.203: U3.6@60.125,18.475 U3.6@60.275,18.475 60.598,18.475 60.875,18.752 R18.1@60.875,19.275
  Top Layer w0.25: R18.1@60.875,19.275 C24.2@61.725,19.275
NetC25_1: C25.1 C28.1 C29.2 C42.1 C44.2 C71.1 | length 12.6
  Top Layer w0.254: C44.2@38.093,10.357 C44.2@38.1,10.35
  Top Layer w0.293: C25.1@37.303,19.431 38.068,19.431 C29.2@38.075,19.425 cw(c36.675,15.975) 40.398,16.012 C28.1@40.398,14.927 C71.1@40.398,13.843 ; C42.1@37.31,10.357 38.093,10.357 ccw(c36.591,13.854) C71.1@40.398,13.843 ; C71.1@40.398,13.798 C71.1@40.398,13.843
NetC25_2: C25.2 L6.2 U2.23 | length 2.6
  Top Layer w0.293: U2.23@34,19.3 35.569,19.3 35.7,19.431 L6.2@35.725,19.431 C25.2@36.503,19.431
NetC26_1: C26.1 U7.5 | length 1.2
  Top Layer w0.293: U7.5@46.95,20.8 C26.1@48.1,20.8
NetC26_2: C26.2 U3.1 | length 12.3
  Top Layer w0.293: C26.2@48.966,20.8 58.125,20.803 ; 58.125,20.8 cw(c58.136,19.276) 59.66,19.286 U3.1@59.66,18.575
NetC27_1: C27.1 U2.3 | length 1.1
  Top Layer w0.2: C27.1@32.2,21.425 32.2,21.05 32.35,20.9 U2.3@32.35,20.45 U2.3@32.35,20.425
NetC27_2: C27.2 R19.1 | length 0.6
  Top Layer w0.2: C27.2@32.2,21.925 R19.1@32.2,22.5
NetC28_2: C28.2 U8.5 | length 1.2
  Top Layer w0.293: C28.2@41.198,14.927 U8.5@42.348,14.927
NetC30_1: C30.1 U3.5 | length 1.2
  Top Layer w0.25: C30.1@61.025,18.075 C30.1@61.2,18.077
  Top Layer w0.293: U3.5@60.15,18.077 60.275,18.077 C30.1@61.2,18.077
NetC30_2: C30.2 C33.1 L5.1 | length 2.1
  Top Layer w0.25: L5.1@62.875,18.075 C33.1@62.875,19.25
  Top Layer w0.293: C30.2@62,18.075 L5.1@62.875,18.075
NetC31_2: C31.2 L14.1 R41.2 U11.1 | length 2.9
  Top Layer w0.15: R41.2@42.926,6.608 42.926,5.942 L14.1@42.92,5.935 42.933,5.922 C31.2@43.815,5.922 43.825,5.912 U11.1@45.09,5.912
NetC32_1: C32.1 U9.2 | length 1.2
  Top Layer w0.293: U9.2@56.475,15.35 C32.1@57.675,15.35
NetC32_2: C32.2 U3.3 | length 2.8
  Top Layer w0.293: C32.2@58.575,15.35 ccw(c58.529,16.481) 59.66,16.527 U3.3@59.66,17.575
NetC34_1: C34.1 D1.1 L5.2 RFIO1.1 | length 9.4
  Top Layer w0.254: 65.486,16.476 cw(c66.462,16.476) 65.486,16.497 ; 65.486,17.239 cw(c64.589,17.178) 65.488,17.175
  Top Layer w0.293: C34.1@63.675,19.25 L5.2@63.675,18.075 64.589,18.075 ; 64.575,18.077 cw(c64.589,17.178) 65.486,17.239 65.486,16.476 ccw(c66.462,16.476) v1(66.475,15.5) 66.475,14.746 D1.1@66.497,14.724
  Bottom Layer w0.293: v1(66.475,15.5) RFIO1.1@69.2,15.5
NetC35_2: C35.2 L6.1 U2.22 | length 2.6
  Top Layer w0.293: U2.22@34,18.8 35.556,18.8 L6.1@35.725,18.631 C35.2@36.503,18.631
NetC36_2: C36.2 L4.2 L7.1 U2.6
NetC39_1: C39.1 R24.1 U3.4 | length 2.2
  Top Layer w0.203: U3.4@60.125,17.675 U3.4@60.275,17.675 60.591,17.675 60.875,17.391 R24.1@60.875,16.9
  Top Layer w0.25: R24.1@60.875,16.9 C39.1@61.725,16.9
NetC41_2: C41.2 L8.1 R25.2 U6.2
  other v1: 29.5,13.225 32.9,13.65
NetC42_2: C42.2 L9.2 U6.23 | length 2.6
  Top Layer w0.293: U6.23@34,10.225 35.563,10.225 35.716,10.378 L9.2@35.738,10.4 ; L9.2@35.728,10.41 L9.2@35.738,10.42 ; L9.2@35.738,10.357 C42.2@36.51,10.357
NetC43_1: C43.1 U6.3 | length 1
  Top Layer w0.2: C43.1@32.225,12.3 C43.1@32.2,12.325 32.2,12 32.35,11.85 U6.3@32.35,11.375
NetC43_2: C43.2 R26.1 | length 0.6
  Top Layer w0.2: C43.2@32.2,12.825 R26.1@32.2,13.4
NetC45_2: C45.2 L9.1 U6.22 | length 2.6
  Top Layer w0.293: U6.22@34,9.725 35.57,9.725 L9.1@35.738,9.557 C45.2@36.51,9.557
NetC46_2: C46.2 L8.2 L10.1 U6.6
NetC48_2: C48.2 FB5.2 Y1.4 | length 1.4
  Top Layer w0.25: C48.2@27.8,25.225 C48.2@27.825,25.2
  Top Layer w0.3: FB5.2@27.125,25.225 C48.2@27.8,25.225 Y1.4@28.45,25.225
NetC49_1: C49.1 FB12.1 RT1.5 | length 2.1
  Top Layer w0.254: RT1.5@36.449,5.129 RT1.5@36.449,5.382 36.449,6.403 C49.1@36.443,6.409 FB12.1@37.24,6.409
NetC52_2: C52.2 FB3.1 L11.2 RT2.C2 | length 5.7
  Top Layer w0.254: C52.2@12.025,12.6 FB3.1@12.675,12.6 ; 12.755,12.084 12.925,11.914 RT2.C2@12.925,11.275
  Bottom Layer w0.508: 12.675,12.75 12.675,11.275 13.675,10.275 v1(13.675,10.2) v1(13.675,9.575) ; v1(12.675,13.1) v1(12.675,13.7)
NetC56_2: C56.2 FB1.1 MCU_H1.1 | length 2
  Top Layer w0.15: MCU_H1.1@7.215,28.1 7.225,28.09 FB1.1@7.225,26.775 7.225,26.075
NetC57_1: C57.1 U11.3 | length 1.1
  Top Layer w0.15: C57.1@44.014,4.928 44.03,4.912 U11.3@45.09,4.912
NetC57_2: C57.2 R44.1 | length 0.6
  Top Layer w0.15: R44.1@42.947,4.928 C57.2@43.514,4.928
NetC58_1: C58.1 FB14.1 RT4.5
NetC60_1: C60.1 Q1.1 U4.3 | length 14.4
  Top Layer w0.15: Q1.1@4.394,25.327 Q1.1@4.429,25.293 ; C60.1@4.621,23.849 4.597,23.873 4.597,25.124 Q1.1@4.429,25.293 ; v1(5.131,25.293) Q1.1@4.429,25.293 ; v1(10.008,18.451) 10.075,18.451 10.09,18.466 10.112,18.443 10.112,18.451 10.112,18.556 10.6,19.044 U4.3@10.6,19.575
  Bottom Layer w0.15: v1(5.131,25.293) 5.131,23.241 5.766,22.606 5.766,20.069 7.685,18.15 9.706,18.15 v1(10.008,18.451)
NetC62_2: C62.2 R32.1 | length 0.7
  Top Layer w0.15: R32.1@14.169,17.145 C62.2@14.859,17.145
NetC64_1: C64.1 R57.2 | length 0.8
  Top Layer w0.15: C64.1@49.672,16.613 R57.2@50.484,16.613
NetC64_2: C64.2 L13.2 R58.1 U10.4 | length 3.4
  Top Layer w0.15: R58.1@48.293,15.363 48.293,15.367 48.293,16.42 48.486,16.613 C64.2@48.872,16.613
  Top Layer w0.293: L13.2@47.917,14.557 47.917,14.747 48.293,15.123 48.293,15.363 48.299,15.356 U10.4@49.059,15.356
NetC65_1: C65.1 U9.5 | length 1.4
  Top Layer w0.293: C65.1@52.8,15.353 52.803,15.35 U9.5@54.175,15.35
NetC65_2: C65.2 L12.2 R57.1 U10.3 | length 3.6
  Top Layer w0.15: R57.1@51.284,16.613 51.664,16.613 52,16.277 C65.2@52,15.353 ; L12.2@51.975,14.45 L12.2@52,14.475
  Top Layer w0.293: U10.3@50.959,15.356 C65.2@51.843,15.356 ; L12.2@51.842,14.557 L12.2@51.846,14.562 ; L12.2@52,14.475 C65.2@52,15.353
NetC66_1: C66.1 R58.2 | length 0.7
  Top Layer w0.293: C66.1@46.678,15.365 46.68,15.363 R58.2@47.375,15.363
NetC66_2: C66.2 U8.2 | length 1.3
  Top Layer w0.293: U8.2@44.648,14.927 44.698,14.978 45.352,14.978 45.725,15.351 45.725,15.367 C66.2@45.725,15.387
NetC67_2: C67.2 L12.1 U10.2 | length 3.1
  Top Layer w0.15: U10.2@50.859,14.856 U10.2@50.959,14.856 51.28,14.856 51.398,14.738 51.398,13.757 51.506,13.65 L12.1@51.975,13.65 C67.2@52.85,13.65 ; C67.2@52.675,13.757 C67.2@52.682,13.751
NetC69_2: C69.2 Q1.2 U4.2 | length 18.2
  Top Layer w0.15: C69.2@1.525,23.891 1.525,25.075 Q1.2@1.835,25.386 1.835,26.361 2.154,26.679 v1(2.718,26.679) ; v1(9.271,18.625) 9.525,18.625 10.1,19.2 U4.2@10.1,19.575
  Bottom Layer w0.15: v1(2.718,26.679) 5.027,26.679 5.715,25.992 5.715,23.41 6.264,22.86 6.264,19.952 7.592,18.625 v1(9.271,18.625)
NetC70_1: C70.1 C71.2 C72.2 | length 8.9
  Top Layer w0.15: C70.1@46.596,9.05 46.596,9.075 C70.1@46.596,9.084
  Top Layer w0.293: C71.2@40.894,13.513 ccw(c45.281,13.438) 45.281,9.051 ; 45.281,9.05 C70.1@46.596,9.05 ; C70.1@46.596,9.075 ccw(c45.764,13.94) C70.1@46.607,9.077 ; C72.2@46.596,9.656 46.596,9.084 ccw(c45.793,13.954) C70.1@46.626,9.089
NetC70_2: C70.2 L15.2 U11.22 | length 2
  Top Layer w0.293: C70.2@46.596,8.55 L15.2@46.596,7.874 46.596,7.388 46.74,7.245 U11.22@46.74,6.562
NetC73_2: C73.2 L15.1 U11.21 | length 2.1
  Top Layer w0.293: U11.21@47.24,6.562 47.24,7.235 47.396,7.391 L15.1@47.396,7.874 C73.2@47.396,8.55
NetC74_2: C74.2 L14.2 L16.1 U11.7 | length 8.2
  Top Layer w0.15: L16.1@42.669,3.8 L16.1@43.028,3.442
  Top Layer w0.254: L14.2@42.12,5.935 41.317,5.935 40.996,5.613 40.996,4.064 41.26,3.8 C74.2@41.725,3.8 L16.1@42.669,3.8 ; L16.1@43.028,3.442 43.404,3.442 44.196,2.65 45.628,2.65 U11.7@45.74,2.762
NetD2_1: D2.1 R45.1 USB_DC_IN1.2 | length 2.6
  Top Layer w0.15: USB_DC_IN1.2@5.4,14.5 R45.1@7.2,14.5
  Top Layer w0.254: D2.1@7.2,13.725 R45.1@7.2,14.5
NetD3_1: D3.1 R46.1 USB_DC_IN1.3 | length 2.5
  Top Layer w0.15: USB_DC_IN1.3@5.4,16.5 R46.1@7.175,16.5
  Top Layer w0.254: R46.1@7.175,16.5 D3.1@7.175,17.275
NetD4_1: D4.1 FB7.1 USB_DC_IN1.4
NetD6_1: D6.1 FB4.1 USB_DC_IN1.1 | length 2
  Top Layer w0.254: USB_DC_IN1.1@5.4,12 6.25,12 6.625,11.625 7.175,11.625 FB4.1@7.2,11.65
NetFB6_2: FB6.2 USB_DC_IN1.6
NetFB15_2: FB15.2 USB_DC_IN1.5
NetL7_2: L7.2 U2.8
NetL10_2: L10.2 U6.8
NetL11_1: L11.1 RT2.A1 | length 2.2
  Top Layer w0.254: L11.1@11.675,8.825 11.675,10.425 RT2.A1@12.125,10.875
NetL13_1: L13.1 R61.1 | length 0.8
  Top Layer w0.293: R61.1@47.917,12.973 L13.1@47.917,13.757
NetL16_2: L16.2 U11.9 | length 4.4
  Top Layer w0.254: L16.2@43.028,1.842 46.419,1.842 46.74,2.162 U11.9@46.74,2.762
NetLED_PWR_1: LED_PWR.1 R42.2 | length 1.3
  Top Layer w0.254: R42.2@24.925,5.025 26.15,5.025 LED_PWR.1@26.175,5
NetLED_RX_1: LED_RX.1 R20.2 | length 0.9
  Top Layer w0.15: LED_RX.1@63,22.85 R20.2@63.9,22.85
NetLED_TX_1: LED_TX.1 R21.1 | length 0.9
  Top Layer w0.15: LED_TX.1@66.5,22.85 R21.1@67.425,22.85
NetR2_1: R2.1 U1.2 | length 1
  Top Layer w0.15: R2.1@17.525,16.025 17.85,16.025 17.975,15.9 U1.2@18.45,15.9
NetR3_1: R3.1 U1.49 | length 13.5
  Top Layer w0.2: U1.49@25.354,15.554 U1.49@25.35,15.55 25.9,15.55 27.3,16.95 27.3,22.3 28.275,23.275 30.95,23.275 31.225,23 31.225,22.25 31.35,22.125 R3.1@31.35,21.9 R3.1@31.35,21.875
NetR4_1: R4.1 U1.48 | length 4.8
  Top Layer w0.2: U1.48@25.325,15.2 U1.48@25.35,15.2 ; 25.797,15.2 U1.48@25.35,15.2 ; R4.1@28.591,17.809 28.591,17.8 28.591,17.766 26.025,15.2 U1.48@25.35,15.2
NetR5_1: R5.1 U1.45 | length 5.5
  Top Layer w0.2: U1.45@25.35,14.15 27.011,14.15 27.8,14.939 27.8,16.361 28.664,17.225 R5.1@28.75,17.225
NetR6_2: R6.2 U1.8 | length 4.9
  Top Layer w0.15: R6.2@13.945,14.497 14.287,14.497 15.059,13.725 17.897,13.725 17.972,13.8 U1.8@18.45,13.8
NetR7_1: R7.1 U1.44 | length 5.3
  Top Layer w0.2: U1.44@25.35,13.8 27.114,13.8 28.125,14.811 28.125,16.05 28.725,16.65 R7.1@28.75,16.65
NetR9_1: R9.1 U1.43 | length 5.2
  Top Layer w0.2: U1.43@25.35,13.45 27.216,13.45 29.316,15.55 R9.1@29.675,15.55
NetR10_1: R10.1 U1.41 | length 11.6
  Top Layer w0.2: U1.41@25.35,12.75 27.375,12.75 29.495,14.87 33.728,14.87 34.976,16.118 R10.1@34.976,16.717
NetR11_1: R11.1 U1.38 | length 9.4
  Top Layer w0.2: U1.38@25.35,11.7 26.075,11.7 26.35,11.425 v1(27.15,11.425) ; R11.1@31.35,12.825 31.45,12.925 31.35,13.025 v1(31.35,13.9)
  MidLayer2 w0.2: v1(27.15,11.425) 30.775,11.425 31.35,12 v1(31.35,13.9)
NetR12_1: R12.1 U1.37 | length 4.6
  Top Layer w0.2: U1.37@25.375,11.35 25.95,11.35 27.62,9.68 27.62,9.53 28.425,8.725 R12.1@28.75,8.725
NetR13_1: R13.1 U1.36 | length 5.2
  Top Layer w0.2: 25.834,11 U1.36@25.35,11 25.847,11 27.25,9.597 27.25,9.425 28.525,8.15 R13.1@28.75,8.15
NetR14_1: R14.1 U1.35 | length 4.9
  Top Layer w0.2: U1.35@25.35,10.65 25.745,10.65 26.925,9.47 26.925,9.15 28.5,7.575 R14.1@28.75,7.575 R14.1@28.75,7.65
NetR15_2: R15.2 U1.32 | length 14
  Top Layer w0.2: U1.32@24,10 24,9.484 24.584,8.9 25.5,8.9 28.598,5.802 33.477,5.802 34.95,7.275 R15.2@34.95,7.7
NetR16_2: R16.2 U1.34 | length 7.1
  Top Layer w0.2: U1.34@24.7,10 25.375,10 28.725,6.65 R16.2@30.45,6.65
NetR22_1: R22.1 R43.2 RT4.3 | length 2.1
  Top Layer w0.508: R22.1@10.043,3.023 10.043,3.843 R43.2@10.05,3.85 RT4.3@11.073,3.85 RT4.3@11.325,3.85
NetR23_2: R23.2 RT2.B1 | length 2.8
  Top Layer w0.25: R23.2@10.475,10.375 v1(11.025,10.375) ; v1(12.506,10.243) v1@12.525,10.262 ; RT2.B1@12.506,10.856 RT2.B1@12.525,10.875
  Top Layer w0.254: v1@12.525,10.262 RT2.B1@12.525,10.875
  Bottom Layer w0.25: v1(11.025,10.375) 11.502,10.375 11.634,10.243 v1(12.506,10.243)
NetR27_2: R27.2 Y1.3 | length 0.6
  Top Layer w0.2: Y1.3@30.275,25.225 R27.2@30.875,25.225
NetR28_1: R28.1 R59.1 R60.1 U10.5 | length 7.2
  Top Layer w0.15: v1(48.753,10.719) R28.1@48.753,11.382 49.584,11.382 R60.1@49.597,11.396 49.611,11.382 R59.1@49.611,10.6 ; v1(48.971,13.575) 48.565,13.981 48.565,14.671 48.75,14.856 U10.5@49.059,14.856 U10.5@49.159,14.856
  MidLayer2 w0.15: v1(48.753,10.719) 48.743,10.729 48.743,11.633 48.971,11.862 v1(48.971,13.575)
NetR31_1: R31.1 U1.51 | length 5.6
  Top Layer w0.15: R31.1@24.575,21.525 24.575,20.7 25.35,19.925 U1.51@25.35,16.25
NetR33_1: R33.1 U1.50 | length 6.2
  Top Layer w0.15: U1.50@25.35,15.9 25.825,15.9 26,16.075 26,20.575 25.825,20.75 R33.1@25.825,21.525
NetR34_1: R34.1 R36.1 SPI_H1.11 | length 3
  Top Layer w0.15: R36.1@11.884,27.502 11.883,27.503 R34.1@11.883,28.127 12.133,28.127 12.255,28.005 v1(12.45,28.005)
  Bottom Layer w0.15: v1(12.45,28.005) 12.675,28.005 SPI_H1.11@13.75,29.08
